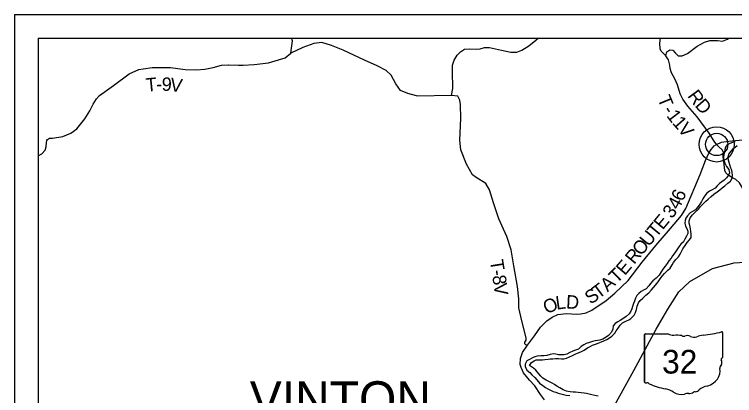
# Model space of a CAD drawing. Extents: x -15 to 405, y -40 to 87.
# Drawn here: x 23.065 to 26.107, y -28.706 to -27.096 of the extents above; entities that cross this region are included whole.
import ezdxf

# ---------------------------------------------------------------- set-up
doc = ezdxf.new("R2010")
doc.units = 0
for name, color, linetype in [('GM_P_State_Location', 7, 'Continuous'), ('GM_X_County_Road_Text', 7, 'Continuous'), ('GM_X_Major_Lake_Text', 7, 'Continuous'), ('GM_X_Minor_Lake', 7, 'Continuous'), ('GM_X_Minor_River', 7, 'Continuous'), ('GM_X_State_Location', 7, 'Continuous'), ('GM_X_Township', 7, 'Continuous'), ('GM_X_Township_Road', 7, 'Continuous'), ('GM_X_Township_Subdivision', 7, 'Continuous'), ('GM_X_Township_Subdivision_Text', 7, 'Continuous'), ('GM_X_Township_Text', 7, 'Continuous')]:
    doc.layers.add(name, color=color, linetype=linetype)

msp = doc.modelspace()

# ---------------------------------------------------------------- linework, layer by layer
at = {"layer": 'GM_P_State_Location'}
for points in [[(24.7641, -27.4393), (24.727, -27.43), (24.6966, -27.4172), (24.6757, -27.3884), (24.6566, -27.3517), (24.635, -27.3321), (24.5974, -27.3125), (24.5446, -27.2883), (24.4543, -27.2469), (24.4042, -27.2269), (24.3643, -27.2141), (24.3298, -27.2191), (24.2833, -27.2348), (24.2326, -27.2588)], [(26.0307, -27.6459), (26.0175, -27.6266), (25.9998, -27.597), (25.9489, -27.5288), (25.9094, -27.4834), (25.888, -27.4535), (25.8775, -27.4318), (25.8656, -27.3929), (25.8541, -27.3682), (25.8411, -27.343), (25.8357, -27.3246), (25.8334, -27.3103), (25.8275, -27.2874), (25.817, -27.2705), (25.8056, -27.2599), (25.7973, -27.2502), (25.7922, -27.2406), (25.7912, -27.2167), (25.7937, -27.1955)], [(25.817, -27.2705), (25.818, -27.2643), (25.8214, -27.2533), (25.8343, -27.2454), (25.846, -27.2472), (25.8556, -27.2582), (25.8692, -27.271), (25.8852, -27.271), (25.9079, -27.2603), (25.9491, -27.2292), (25.9801, -27.2128), (26.0028, -27.2059), (26.0343, -27.2062), (26.0559, -27.208), (26.0771, -27.2), (26.0826, -27.1955)], [(23.9701, -27.3081), (23.9702, -27.3081), (23.9711, -27.308), (24.0112, -27.3101), (24.0317, -27.3097), (24.078, -27.3073), (24.1383, -27.3001), (24.2085, -27.2785), (24.2326, -27.2588)], [(23.6088, -27.3255), (23.6469, -27.3196), (23.7248, -27.3197), (23.7865, -27.3285), (23.8342, -27.3298), (23.8694, -27.327), (23.905, -27.3193), (23.9401, -27.3104), (23.9701, -27.3081)], [(25.2266, -28.4718), (25.227, -28.4713), (25.2274, -28.4622), (25.2078, -28.3902), (25.1955, -28.3349), (25.1954, -28.2966), (25.1899, -28.2458), (25.1748, -28.1572), (25.164, -28.0897), (25.1452, -28.0344), (25.112, -27.959), (25.0894, -27.892), (25.0725, -27.8371), (25.0565, -27.8094), (25.0159, -27.7849), (25.0007, -27.7732), (24.9751, -27.7285), (24.951, -27.6679), (24.9464, -27.6262), (24.9502, -27.5348), (24.9497, -27.4765), (24.9473, -27.4575), (24.9382, -27.4409), (24.9111, -27.4384), (24.9093, -27.4383), (24.7691, -27.4405), (24.7641, -27.4393), (24.7641, -27.4393)], [(25.2328, -28.4933), (25.226, -28.4914), (25.2214, -28.4869), (25.2206, -28.4797), (25.2264, -28.4721), (25.2266, -28.4718)]]:
    msp.add_lwpolyline(points, dxfattribs=at)
at = {"layer": 'GM_X_Major_Lake_Text'}
for points in [[(24.2326, -27.2588), (24.2392, -27.2068), (24.2362, -27.1955)], [(24.9111, -27.4384), (24.9172, -27.4079), (24.9158, -27.3348), (24.915, -27.3098), (24.9225, -27.2893), (24.9349, -27.268), (24.9489, -27.254), (24.9667, -27.2418), (24.9868, -27.2414), (25.0171, -27.2428), (25.0319, -27.2416), (25.0512, -27.2348), (25.0717, -27.2355), (25.1232, -27.2463), (25.1627, -27.2546), (25.1877, -27.2557), (25.2089, -27.2465), (25.2384, -27.2279), (25.2679, -27.2039), (25.2772, -27.1955)], [(23.1652, -27.6936), (23.1804, -27.6843), (23.1951, -27.6698), (23.1999, -27.6546), (23.2014, -27.6372), (23.2028, -27.6285), (23.2051, -27.6235), (23.2138, -27.6178), (23.2255, -27.6185), (23.2694, -27.6108), (23.3037, -27.5973), (23.329, -27.5794), (23.3621, -27.5365), (23.3843, -27.5026), (23.3978, -27.4749), (23.4113, -27.4517), (23.4249, -27.438), (23.4834, -27.3961), (23.5501, -27.3462), (23.5913, -27.3282), (23.6086, -27.3255), (23.6088, -27.3255)]]:
    msp.add_lwpolyline(points, dxfattribs=at)
at = {"layer": 'GM_X_State_Location'}
msp.add_lwpolyline([(25.6, -28.7475), (25.681, -28.6), (25.776, -28.4258), (25.8247, -28.341), (25.8721, -28.2679), (25.9179, -28.2241), (26.0132, -28.1694), (26.1048, -28.1452), (26.1735, -28.1414)], dxfattribs=at)
at = {"layer": 'GM_X_Township'}
for p, q in [((23.0652, -27.0955), (30.0652, -27.0955)), ((23.0652, -27.0955), (23.0652, -34.0955)), ((23.1652, -27.1955), (23.1652, -33.9955)), ((23.1652, -27.1955), (29.9652, -27.1955))]:
    msp.add_line(p, q, dxfattribs=at)
at = {"layer": 'GM_X_Township_Road'}
for points in [[(25.555, -28.4749), (25.5675, -28.4692), (25.5789, -28.462), (25.5884, -28.4544), (25.601, -28.4419), (25.6071, -28.4324), (25.615, -28.4214), (25.6238, -28.4089), (25.6344, -28.3987), (25.6477, -28.3919), (25.6599, -28.3866), (25.6694, -28.3801), (25.6831, -28.3661), (25.6884, -28.3551), (25.6922, -28.3422), (25.696, -28.3282), (25.7013, -28.3145), (25.7082, -28.3039), (25.7192, -28.2944), (25.7329, -28.2823), (25.7447, -28.2713), (25.7568, -28.2595), (25.7644, -28.2493), (25.7728, -28.2398), (25.785, -28.225), (25.793, -28.2132), (25.8006, -28.2019), (25.8108, -28.1905), (25.8253, -28.1761), (25.8352, -28.1677), (25.8439, -28.1541), (25.8492, -28.1438), (25.8584, -28.1306), (25.8701, -28.1192), (25.877, -28.1089), (25.8823, -28.0972), (25.8884, -28.0858), (25.8987, -28.0722), (25.9074, -28.0596), (25.9173, -28.0479), (25.9234, -28.038), (25.9242, -28.0228), (25.923, -28.0122), (25.9208, -28.002), (25.9174, -27.9879), (25.9155, -27.9781), (25.9151, -27.9671), (25.9197, -27.9545), (25.9288, -27.9424), (25.9413, -27.9318), (25.9543, -27.9185), (25.9634, -27.9075), (25.9755, -27.895), (25.9851, -27.8844), (25.9953, -27.876), (26.0082, -27.8643), (26.0189, -27.8552), (26.0329, -27.845), (26.0447, -27.837), (26.0546, -27.8283), (26.0656, -27.8196), (26.0782, -27.8089), (26.0892, -27.7995), (26.0972, -27.7869), (26.0983, -27.7744), (26.0968, -27.7638), (26.0949, -27.7543), (26.0919, -27.7448), (26.0874, -27.7315), (26.0847, -27.7217), (26.0821, -27.711), (26.0802, -27.6985), (26.0832, -27.686), (26.092, -27.6731), (26.1026, -27.6614), (26.1186, -27.6492)], [(26.1099, -27.634), (26.0981, -27.6374), (26.0875, -27.6408), (26.0761, -27.6462), (26.0684, -27.6564), (26.0662, -27.667), (26.0646, -27.6769), (26.0623, -27.6879), (26.0608, -27.6996), (26.0612, -27.7118), (26.0657, -27.7247), (26.0733, -27.7376), (26.0832, -27.7513), (26.0854, -27.7649), (26.0809, -27.7752), (26.0729, -27.7854), (26.063, -27.796), (26.0535, -27.8032), (26.044, -27.8097), (26.033, -27.8203), (26.0246, -27.8298), (26.0102, -27.8381), (26.0007, -27.843), (25.9904, -27.8502), (25.9798, -27.8639), (25.9733, -27.8753), (25.9672, -27.8855), (25.96, -27.8973), (25.952, -27.909), (25.9417, -27.9212), (25.9292, -27.9284), (25.9197, -27.934), (25.9083, -27.9466), (25.9018, -27.956), (25.8988, -27.9663), (25.8972, -27.9777), (25.9003, -27.9898), (25.9056, -28.0008), (25.9094, -28.0114), (25.909, -28.0209), (25.904, -28.0327), (25.8976, -28.0456), (25.8907, -28.0558), (25.8801, -28.0664), (25.8717, -28.0778), (25.8626, -28.0907), (25.8542, -28.1029), (25.8455, -28.1154), (25.839, -28.1249), (25.8299, -28.1374), (25.8223, -28.148), (25.8135, -28.1586), (25.804, -28.1723), (25.7968, -28.1836), (25.788, -28.1969), (25.7759, -28.2102), (25.7618, -28.2219), (25.7519, -28.2322), (25.7451, -28.2424), (25.7337, -28.2553), (25.723, -28.2606), (25.7128, -28.2667), (25.7033, -28.2743), (25.6945, -28.2837), (25.6892, -28.2948), (25.6839, -28.3069), (25.6808, -28.3175), (25.6766, -28.3293), (25.6728, -28.3395), (25.669, -28.349), (25.6614, -28.3608), (25.6496, -28.3718), (25.6348, -28.3816), (25.6234, -28.3888)], [(25.6234, -28.3888), (25.6135, -28.3949), (25.6033, -28.4017), (25.5938, -28.4119), (25.5922, -28.426), (25.5877, -28.4385), (25.5751, -28.4522), (25.5653, -28.459), (25.5508, -28.4677), (25.5383, -28.4715), (25.5284, -28.4734), (25.5182, -28.4753), (25.5068, -28.4775), (25.4942, -28.4817), (25.4809, -28.4862), (25.4699, -28.4915), (25.4597, -28.498), (25.4483, -28.5097), (25.4346, -28.5147), (25.4236, -28.5181), (25.411, -28.5241), (25.3992, -28.5313), (25.3875, -28.534), (25.3761, -28.5344), (25.3628, -28.5332), (25.3522, -28.5313), (25.3412, -28.5298), (25.3275, -28.532), (25.3146, -28.5373), (25.3009, -28.5385), (25.2884, -28.5388), (25.2739, -28.5396), (25.2637, -28.5419), (25.2534, -28.5468), (25.2432, -28.5521), (25.2299, -28.5597), (25.2223, -28.5733), (25.2219, -28.5836), (25.2294, -28.598), (25.2423, -28.6086), (25.2507, -28.6181), (25.2636, -28.6303), (25.2712, -28.6402), (25.2833, -28.6531), (25.2977, -28.6633), (25.3091, -28.6713), (25.319, -28.6778), (25.341, -28.6888), (25.3516, -28.6922), (25.3622, -28.6953), (25.3736, -28.6987), (25.3846, -28.7014), (25.3964, -28.7048), (25.4108, -28.7063)], [(25.5304, -28.7091), (25.5168, -28.706), (25.5039, -28.703), (25.4932, -28.7007), (25.4822, -28.6976), (25.4712, -28.6957), (25.4591, -28.6942), (25.4465, -28.693), (25.4348, -28.6923), (25.4253, -28.6915), (25.412, -28.6896), (25.3968, -28.6869), (25.3831, -28.6816), (25.3687, -28.674), (25.3562, -28.6657), (25.346, -28.6596), (25.3361, -28.6531), (25.3228, -28.6463), (25.311, -28.641), (25.2978, -28.6318), (25.2883, -28.6242), (25.2799, -28.6147), (25.2678, -28.5984), (25.2572, -28.5897), (25.2412, -28.5787), (25.25, -28.5658), (25.2602, -28.5597), (25.2697, -28.5544), (25.2819, -28.5544), (25.2956, -28.5556), (25.3054, -28.5537), (25.3191, -28.5518), (25.3286, -28.5514), (25.3392, -28.5507), (25.3514, -28.5495), (25.3632, -28.5499), (25.3757, -28.5514), (25.3856, -28.5507), (25.3977, -28.5477), (25.4102, -28.5427), (25.4232, -28.5367), (25.4342, -28.531), (25.4463, -28.5257), (25.4577, -28.5215), (25.4722, -28.5143), (25.4858, -28.5045), (25.4969, -28.4984), (25.5067, -28.4935), (25.5193, -28.4885), (25.5314, -28.484), (25.5444, -28.4791), (25.555, -28.4749)]]:
    msp.add_lwpolyline(points, dxfattribs=at)
at = {"layer": 'GM_X_Township_Subdivision'}
for p, q in [((26.0565, -28.4402), (26.0565, -28.5449)), ((25.7269, -28.4486), (25.7269, -28.6487)), ((25.7269, -28.6487), (25.7269, -28.4486)), ((25.7269, -28.6487), (25.7269, -28.4486)), ((25.7302, -28.4452), (25.8267, -28.4452)), ((26.0565, -28.5449), (26.0565, -28.5449))]:
    msp.add_line(p, q, dxfattribs=at)
for centre, major_axis, start_param, end_param in [((25.9391, -28.1723), (0.3495, 0), 4.814394, 5.042369), ((26.0529, -28.4398), (0.00367, 0), 6.141152, 7.989035), ((25.7307, -28.4482), (0.00382, 0), 1.712693, 3.28349), ((25.8497, -28.4219), (0.037, 0), 4.042523, 4.731795), ((25.862, -28.5575), (0.133, 0), 1.404758, 1.657858), ((25.8921, -28.4471), (0.0107, 0), 3.836095, 5.185415), ((25.9078, -28.4703), (0.0222, 0), 0.950623, 2.079405), ((25.9365, -28.4385), (0.0267, 0), 4.081561, 5.145723), ((25.9837, -28.5063), (0.0703, 0), 1.699011, 2.107814), ((26.0557, -28.5526), (0.00568, 0), 1.883978, 3.671073), ((26.0195, -28.5658), (0.0341, 0), 5.934695, 6.695948), ((26.0526, -28.5453), (0.00393, 0), 5.05454, 6.418171), ((25.9587, -28.602), (0.0874, 0), 5.101752, 6.440018), ((26.0697, -28.5887), (0.0248, 0), 2.387724, 3.262537), ((25.7307, -28.6492), (0.00385, 0), 3.00124, 4.508301), ((25.7313, -28.6287), (0.0294, 0), 4.665946, 4.897461), ((25.7373, -28.6603), (0.0106, 0), 0.519207, 1.627899), ((25.8712, -28.4805), (0.2524, 0), 4.195997, 4.488961), ((25.7959, -28.7386), (0.079, 0), 0.823519, 1.323587), ((25.9349, -28.6681), (0.0282, 0), 4.937069, 5.64225), ((25.9956, -28.7049), (0.0479, 0), 1.647645, 2.488434), ((25.8813, -28.6613), (0.0501, 0), 4.026481, 4.996735), ((25.9103, -28.7305), (0.0412, 0), 1.495662, 1.94098), ((25.9139, -28.6762), (0.0267, 0), 4.691044, 5.507374), ((25.9381, -28.6956), (0.00752, 0), 1.147584, 2.315152)]:
    msp.add_ellipse(centre, major_axis=major_axis, ratio=0.8, start_param=start_param, end_param=end_param, dxfattribs=at)
at = {"layer": 'GM_X_Township_Subdivision_Text'}
for radius in [0.0744, 0.0472]:
    msp.add_circle((26.0316, -27.6448), radius, dxfattribs=at)
at = {"layer": 'GM_X_Township_Text'}
for points in [[(25.3044, -28.724), (25.2877, -28.7009), (25.2637, -28.6642), (25.2409, -28.6408), (25.2161, -28.6097), (25.205, -28.5878), (25.2012, -28.5741), (25.203, -28.5495), (25.212, -28.5244), (25.2328, -28.4933), (25.2618, -28.4534), (25.2871, -28.417), (25.3139, -28.39), (25.3362, -28.3751), (25.3612, -28.3641), (25.3976, -28.3587), (25.44, -28.362), (25.4582, -28.3612), (25.4798, -28.357), (25.5037, -28.3455), (25.5649, -28.3041), (25.6012, -28.2729), (25.6575, -28.2193), (25.7171, -28.1422), (25.7745, -28.0715), (25.836, -28.0001), (25.8832, -27.9454), (25.901, -27.9154), (25.9611, -27.7719), (25.9848, -27.7127), (25.9987, -27.6824), (26.0088, -27.6661), (26.0146, -27.6576), (26.0208, -27.6505), (26.0307, -27.6459), (26.0513, -27.6353), (26.0829, -27.6306), (26.1547, -27.624)], [(26.0615, -27.7163), (26.0594, -27.6976), (26.0599, -27.6769), (26.0546, -27.6676), (26.0407, -27.6552), (26.0307, -27.6459)], [(26.0986, -27.7864), (26.078, -27.7739), (26.0699, -27.765), (26.0656, -27.7547), (26.063, -27.7295), (26.0615, -27.7163)], [(26.1735, -28.1414), (26.1719, -28.1034), (26.1721, -28.0609), (26.1776, -28.021), (26.1833, -27.9928), (26.1852, -27.9745), (26.1872, -27.9454), (26.1874, -27.9288), (26.1831, -27.9074), (26.174, -27.8853), (26.1465, -27.8386), (26.1285, -27.8074), (26.1126, -27.793), (26.0986, -27.7864)]]:
    msp.add_lwpolyline(points, dxfattribs=at)

# ---------------------------------------------------------------- texts
at = {"layer": 'GM_X_County_Road_Text'}
msp.add_text('VINTON', height=0.15152, rotation=0, dxfattribs=at).set_placement((24.0593, -28.7972))
at = {"layer": 'GM_X_Minor_Lake'}
for s, rotation, p in [('6', 66.9639, (25.8888, -27.8888)), ('4', 62.1991, (25.8702, -27.9244)), ('3', 51.4978, (25.8421, -27.9615)), ('E', 50.5184, (25.8033, -28.0087)), ('T', 50.5209, (25.7763, -28.0415)), ('U', 50.521, (25.7445, -28.0801)), ('O', 50.513, (25.7127, -28.1187)), ('R', 50.5196, (25.683, -28.1547)), ('E', 49.4401, (25.6435, -28.2014)), ('T', 44.5967, (25.6097, -28.235)), ('T', 36.9438, (25.5325, -28.2996)), ('A', 42.292, (25.5709, -28.2704)), ('S', 34.84, (25.4991, -28.3229)), ('L', 7.9107, (25.3551, -28.3434)), ('D', 357.2962, (25.3944, -28.3377)), ('O', 24.7988, (25.3139, -28.3631))]:
    msp.add_text(s, height=0.0568, rotation=rotation, dxfattribs=at).set_placement(p)
at = {"layer": 'GM_X_Minor_River'}
for s, rotation, p in [('T', 5.4854, (23.623, -27.4223)), ('9', 358.3034, (23.6868, -27.4181)), ('V', 352.3201, (23.7202, -27.419)), ('-', 0.4215, (23.664, -27.4183)), ('T', 292.4254, (25.7801, -27.4514)), ('R', 306.172, (25.9058, -27.4402)), ('D', 311.266, (25.9368, -27.4821)), ('-', 303.0381, (25.8016, -27.5008)), ('1', 307.6405, (25.8172, -27.5244)), ('1', 311.4843, (25.8412, -27.5553)), ('V', 308.7463, (25.864, -27.581)), ('T', 279.0889, (25.0729, -28.1359)), ('8', 278.8609, (25.0833, -28.2009)), ('-', 279.0299, (25.0796, -28.1779)), ('V', 277.7391, (25.0886, -28.2352))]:
    msp.add_text(s, height=0.0568, rotation=rotation, dxfattribs=at).set_placement(p)
at = {"layer": 'GM_X_Township_Subdivision'}
msp.add_text('32', height=0.1, dxfattribs=at).set_placement((25.8009, -28.613))

doc.saveas('drawing.dxf')
